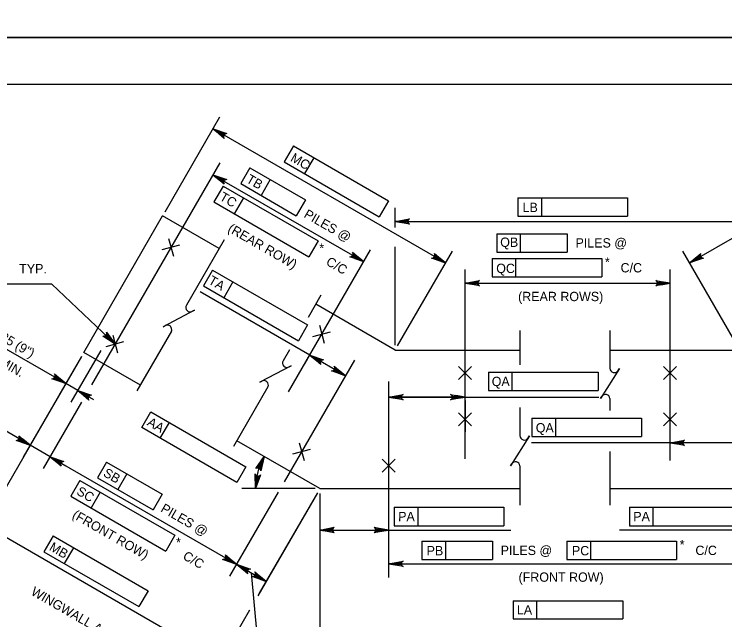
# Model space of a CAD drawing. Extents: x 638340 to 640241, y 295465 to 298435.
# Drawn here: x 639424.7 to 639653.4, y 296465.9 to 296661 of the extents above; entities that cross this region are included whole.
import ezdxf

# ---------------------------------------------------------------- set-up
doc = ezdxf.new("R2010")
doc.units = 0
for name, color, linetype in [('2', 7, 'Continuous'), ('3', 7, 'Continuous'), ('4', 7, 'Continuous'), ('PLT-BNDY', 7, 'Continuous')]:
    doc.layers.add(name, color=color, linetype=linetype)

# ---------------------------------------------------------------- blocks, each defined once
blk = doc.blocks.new('PILE')
at = {"layer": '2'}
for p, q in [((-2.651625, -2.651625), (2.651625, 2.651625)), ((-2.651625, 2.651625), (2.651625, -2.651625))]:
    blk.add_line(p, q, dxfattribs=at)

msp = doc.modelspace()

# ---------------------------------------------------------------- linework, layer by layer
at = {"layer": '2'}
for p, q in [((639316.46, 296638.46), (640102.69, 296638.46)), ((639473.25, 296597.31), (639490.91, 296627.89)), ((639563.54, 296580.84), (639488.7, 296624.05)), ((639642.12, 296580.84), (639716.97, 296624.05)), ((639514.6, 296618.51), (639511.65, 296613.39)), ((639514.6, 296618.51), (639545.17, 296600.85)), ((639490.89, 296613.09), (639449.6, 296541.57)), ((639511.65, 296613.39), (639542.22, 296595.74)), ((639521.15, 296614.72), (639518.2, 296609.61)), ((639500.56, 296611.49), (639497.61, 296606.38)), ((639500.56, 296611.49), (639518.44, 296601.17)), ((639488.68, 296609.26), (639537.18, 296581.25)), ((639497.61, 296606.38), (639515.49, 296596.06)), ((639507.11, 296607.71), (639504.16, 296602.6)), ((639491.96, 296605.59), (639489, 296600.48)), ((639491.96, 296605.59), (639522.52, 296587.93)), ((639498.5, 296601.81), (639495.55, 296596.7)), ((639518.44, 296601.17), (639515.49, 296596.06)), ((639586.82, 296601.76), (639622.12, 296601.76)), ((639586.82, 296601.76), (639586.82, 296595.85)), ((639594.38, 296601.76), (639594.38, 296595.85)), ((639622.12, 296601.76), (639622.12, 296595.85)), ((639489, 296600.48), (639519.57, 296582.81)), ((639545.17, 296600.85), (639542.22, 296595.74)), ((639547.33, 296592.21), (639547.33, 296598.59)), ((639586.82, 296595.85), (639622.12, 296595.85)), ((639547.33, 296594.16), (639658.34, 296594.16)), ((639580.02, 296590.26), (639580.02, 296584.36)), ((639580.02, 296590.26), (639602.72, 296590.26)), ((639587.58, 296590.26), (639587.58, 296584.36)), ((639602.72, 296590.26), (639602.72, 296584.36)), ((639522.52, 296587.93), (639519.57, 296582.81)), ((639547.33, 296554.3), (639547.33, 296586)), ((639513, 296539.37), (639539.4, 296585.09)), ((639548.1, 296554.09), (639565.76, 296584.68)), ((639580.02, 296584.36), (639602.72, 296584.36)), ((639657.57, 296554.09), (639639.91, 296584.68)), ((639578.51, 296582.25), (639613.81, 296582.25)), ((639578.51, 296582.25), (639578.51, 296576.34)), ((639586.07, 296582.25), (639586.07, 296576.34)), ((639613.81, 296582.25), (639613.81, 296576.34)), ((639488.58, 296578.53), (639485.62, 296573.42)), ((639488.58, 296578.53), (639519.14, 296560.86)), ((639569.83, 296517.7), (639569.83, 296578.72)), ((639635.84, 296517.22), (639635.84, 296578.72)), ((639578.51, 296576.34), (639613.81, 296576.34)), ((639495.13, 296574.75), (639492.17, 296569.63)), ((639569.83, 296574.29), (639635.84, 296574.29)), ((639519.82, 296551.18), (639484.54, 296571.54)), ((639485.62, 296573.42), (639516.19, 296555.75)), ((639519.14, 296560.86), (639516.19, 296555.75)), ((639441.31, 296541.99), (639415.68, 296556.79)), ((639518.32, 296548.58), (639522.03, 296555.01)), ((639452.57, 296552.63), (639442.94, 296535.94)), ((639531.34, 296544.52), (639519.82, 296551.18)), ((639446.34, 296550.69), (639412.82, 296492.63)), ((639446.34, 296550.69), (639427.63, 296518.28)), ((639446.34, 296550.69), (639439.1, 296538.15)), ((639534.22, 296549.5), (639511.6, 296510.33)), ((639577.35, 296545.62), (639612.65, 296545.62)), ((639577.35, 296545.62), (639577.35, 296539.71)), ((639584.91, 296545.62), (639584.91, 296539.71)), ((639612.65, 296545.62), (639612.65, 296539.71)), ((639445.15, 296539.77), (639441.32, 296541.99)), ((639545.22, 296542.69), (639545.22, 296479.48)), ((639429.84, 296522.12), (639396.39, 296541.43)), ((639445.15, 296539.77), (639450.27, 296536.82)), ((639577.35, 296539.71), (639612.65, 296539.71)), ((639545.22, 296537.62), (639612.84, 296537.62)), ((639566.88, 296537.62), (639548.18, 296537.62)), ((639446.36, 296535.96), (639434.02, 296514.59)), ((639545.22, 296536.55), (639545.22, 296526.47)), ((639569.83, 296536.55), (639569.83, 296526.47)), ((639465.78, 296527.78), (639468.74, 296532.89)), ((639468.74, 296532.89), (639499.29, 296515.21)), ((639591.33, 296530.89), (639626.63, 296530.89)), ((639591.33, 296530.89), (639591.33, 296524.98)), ((639598.89, 296530.89), (639598.89, 296524.98)), ((639626.63, 296530.89), (639626.63, 296524.98)), ((639471.71, 296524.35), (639474.66, 296529.47)), ((639496.34, 296510.1), (639465.78, 296527.78)), ((639591.33, 296524.98), (639626.63, 296524.98)), ((639436.24, 296518.42), (639429.84, 296522.11)), ((639635.84, 296522.88), (639591.2, 296522.88)), ((639660.44, 296522.88), (639635.84, 296522.88)), ((639436.24, 296518.42), (639496.27, 296483.76)), ((639438.79, 296516.95), (639441.35, 296515.47)), ((639454.47, 296516.7), (639451.51, 296511.59)), ((639454.47, 296516.7), (639472.35, 296506.38)), ((639499.29, 296515.21), (639496.34, 296510.1)), ((639461.01, 296512.93), (639458.06, 296507.81)), ((639445.86, 296510.8), (639442.91, 296505.69)), ((639445.86, 296510.8), (639476.43, 296493.14)), ((639451.51, 296511.59), (639469.39, 296501.27)), ((639521.54, 296508.16), (639497.97, 296508.16)), ((639442.91, 296505.69), (639473.47, 296488.02)), ((639452.41, 296507.02), (639449.46, 296501.91)), ((639472.35, 296506.38), (639469.39, 296501.27)), ((639509.68, 296507), (639494.05, 296479.93)), ((639522.31, 296506.83), (639503.12, 296473.6)), ((639522.31, 296506.83), (639503.59, 296474.42)), ((639523.08, 296506.62), (639523.08, 296460.33)), ((639547.03, 296502.12), (639582.34, 296502.12)), ((639547.03, 296502.12), (639547.03, 296496.21)), ((639554.6, 296502.12), (639554.6, 296496.21)), ((639582.34, 296502.12), (639582.34, 296496.21)), ((639622.71, 296502.12), (639658.01, 296502.12)), ((639622.71, 296502.12), (639622.71, 296496.21)), ((639630.27, 296502.12), (639630.27, 296496.21)), ((639491, 296452.61), (639415.03, 296496.47)), ((639523.08, 296497.73), (639523.08, 296486.65)), ((639547.03, 296496.21), (639582.34, 296496.21)), ((639622.71, 296496.21), (639658.01, 296496.21)), ((639523.08, 296494.81), (639584.61, 296494.81)), ((639682.78, 296494.81), (639619.52, 296494.81)), ((639437.23, 296492.91), (639434.28, 296487.79)), ((639437.23, 296492.91), (639467.81, 296475.25)), ((639476.43, 296493.14), (639473.47, 296488.02)), ((639443.78, 296489.12), (639440.83, 296484.01)), ((639555.94, 296491.22), (639555.94, 296485.31)), ((639555.94, 296491.22), (639578.64, 296491.22)), ((639563.5, 296491.22), (639563.5, 296485.31)), ((639578.64, 296491.22), (639578.64, 296485.31)), ((639602.6, 296491.22), (639637.9, 296491.22)), ((639602.6, 296491.22), (639602.6, 296485.31)), ((639610.16, 296491.22), (639610.16, 296485.31)), ((639637.9, 296491.22), (639637.9, 296485.31)), ((639434.28, 296487.79), (639464.85, 296470.14)), ((639555.94, 296485.31), (639578.64, 296485.31)), ((639602.6, 296485.31), (639637.9, 296485.31)), ((639496.27, 296483.76), (639505.81, 296478.25)), ((639545.22, 296483.91), (639660.44, 296483.91)), ((639500.99, 296481.03), (639502.81, 296461.18)), ((639467.81, 296475.25), (639464.85, 296470.14)), ((639585.28, 296472.05), (639620.58, 296472.05)), ((639585.28, 296472.05), (639585.28, 296466.15)), ((639592.84, 296472.05), (639592.84, 296466.15)), ((639620.58, 296472.05), (639620.58, 296466.15)), ((639500.46, 296468.98), (639488.79, 296448.77)), ((639585.28, 296466.15), (639620.58, 296466.15))]:
    msp.add_line(p, q, dxfattribs=at)
for points in [[(639491.5, 296623), (639491.01, 296622.15), (639488.7, 296624.05)], [(639491.48, 296608.2), (639490.99, 296607.35), (639488.68, 296609.26)], [(639550.28, 296594.65), (639550.28, 296593.67), (639547.33, 296594.16)], [(639534.87, 296583.16), (639534.38, 296582.3), (639537.18, 296581.25)], [(639561.23, 296582.74), (639560.74, 296581.89), (639563.54, 296580.84)], [(639644.43, 296582.74), (639644.93, 296581.89), (639642.12, 296580.84)], [(639572.78, 296574.79), (639572.78, 296573.8), (639569.83, 296574.29)], [(639632.88, 296574.79), (639632.88, 296573.8), (639635.84, 296574.29)], [(639457.19, 296554.72), (639455.22, 296556.93), (639454.88, 296556.58)], [(639522.62, 296550.13), (639522.13, 296549.27), (639519.82, 296551.18)], [(639529.03, 296546.42), (639528.54, 296545.57), (639531.35, 296544.52)], [(639439, 296543.89), (639438.51, 296543.04), (639441.32, 296541.99)], [(639447.95, 296538.72), (639447.46, 296537.87), (639445.15, 296539.77)], [(639548.18, 296538.11), (639548.18, 296537.12), (639545.22, 296537.62)], [(639566.88, 296538.11), (639566.88, 296537.12), (639569.83, 296537.62)], [(639427.53, 296524.02), (639427.04, 296523.16), (639429.84, 296522.11)], [(639638.79, 296523.38), (639638.79, 296522.39), (639635.84, 296522.88)], [(639439.04, 296517.37), (639438.55, 296516.52), (639436.24, 296518.42)], [(639439.04, 296517.37), (639438.55, 296516.52), (639436.24, 296518.42)], [(639526.03, 296495.3), (639526.03, 296494.32), (639523.08, 296494.81)], [(639542.27, 296495.3), (639542.27, 296494.32), (639545.22, 296494.81)], [(639493.95, 296485.67), (639493.46, 296484.81), (639496.27, 296483.76)], [(639499.07, 296482.71), (639498.58, 296481.86), (639496.27, 296483.76)], [(639548.18, 296484.4), (639548.18, 296483.42), (639545.22, 296483.91)], [(639503.5, 296480.15), (639503.01, 296479.3), (639505.81, 296478.25)]]:
    msp.add_lwpolyline(points, close=True, dxfattribs=at)
for points in [[(639488.7, 296624.05), (639493.17, 296622.48), (639492.73, 296622.44), (639492.42, 296622.27), (639492.22, 296622.02), (639492.1, 296621.72), (639492.11, 296621.36), (639492.3, 296620.97), (639488.7, 296624.05), (639492.11, 296621.36), (639492.1, 296621.72), (639488.7, 296624.05), (639492.22, 296622.02), (639492.42, 296622.27), (639488.7, 296624.05), (639492.73, 296622.44)], [(639488.68, 296609.26), (639493.15, 296607.68), (639492.72, 296607.65), (639492.4, 296607.47), (639492.2, 296607.23), (639492.09, 296606.93), (639492.09, 296606.56), (639492.28, 296606.17), (639488.68, 296609.26), (639492.09, 296606.56), (639492.09, 296606.93), (639488.68, 296609.26), (639492.2, 296607.23), (639492.4, 296607.47), (639488.68, 296609.26), (639492.72, 296607.65)], [(639547.33, 296594.16), (639551.99, 296595.04), (639551.63, 296594.79), (639551.45, 296594.47), (639551.39, 296594.16), (639551.45, 296593.85), (639551.63, 296593.54), (639551.99, 296593.29), (639547.33, 296594.16), (639551.63, 296593.54), (639551.45, 296593.85), (639547.33, 296594.16), (639551.39, 296594.16), (639551.45, 296594.47), (639547.33, 296594.16), (639551.63, 296594.79)], [(639537.18, 296581.25), (639532.71, 296582.82), (639533.14, 296582.86), (639533.46, 296583.04), (639533.66, 296583.28), (639533.77, 296583.58), (639533.77, 296583.94), (639533.58, 296584.34), (639537.18, 296581.25), (639533.77, 296583.94), (639533.77, 296583.58), (639537.18, 296581.25), (639533.66, 296583.28), (639533.46, 296583.04), (639537.18, 296581.25), (639533.14, 296582.86)], [(639563.54, 296580.84), (639559.07, 296582.41), (639559.51, 296582.45), (639559.82, 296582.63), (639560.02, 296582.87), (639560.13, 296583.17), (639560.13, 296583.53), (639559.94, 296583.93), (639563.54, 296580.84), (639560.13, 296583.53), (639560.13, 296583.17), (639563.54, 296580.84), (639560.02, 296582.87), (639559.82, 296582.63), (639563.54, 296580.84), (639559.51, 296582.45)], [(639642.12, 296580.84), (639645.72, 296583.93), (639645.54, 296583.53), (639645.53, 296583.17), (639645.64, 296582.87), (639645.84, 296582.63), (639646.16, 296582.45), (639646.6, 296582.41), (639642.12, 296580.84), (639646.16, 296582.45), (639645.84, 296582.63), (639642.12, 296580.84), (639645.64, 296582.87), (639645.53, 296583.17), (639642.12, 296580.84), (639645.54, 296583.53)], [(639457.19, 296554.72), (639436.85, 296574.04), (639370.27, 296574.04)], [(639569.83, 296574.29), (639574.49, 296575.17), (639574.13, 296574.92), (639573.95, 296574.61), (639573.89, 296574.29), (639573.95, 296573.98), (639574.13, 296573.67), (639574.49, 296573.42), (639569.83, 296574.29), (639574.13, 296573.67), (639573.95, 296573.98), (639569.83, 296574.29), (639573.89, 296574.29), (639573.95, 296574.61), (639569.83, 296574.29), (639574.13, 296574.92)], [(639635.84, 296574.29), (639631.18, 296573.42), (639631.53, 296573.67), (639631.72, 296573.98), (639631.77, 296574.29), (639631.72, 296574.61), (639631.53, 296574.92), (639631.18, 296575.17), (639635.84, 296574.29), (639631.53, 296574.92), (639631.72, 296574.61), (639635.84, 296574.29), (639631.77, 296574.29), (639631.72, 296573.98), (639635.84, 296574.29), (639631.53, 296573.67)], [(639457.19, 296554.72), (639453.21, 296557.3), (639453.64, 296557.23), (639453.99, 296557.33), (639454.25, 296557.52), (639454.42, 296557.78), (639454.5, 296558.14), (639454.42, 296558.57), (639457.19, 296554.72), (639454.5, 296558.14), (639454.42, 296557.78), (639457.19, 296554.72), (639454.25, 296557.52), (639453.99, 296557.33), (639457.19, 296554.72), (639453.64, 296557.23)], [(639519.82, 296551.18), (639524.29, 296549.6), (639523.85, 296549.57), (639523.54, 296549.39), (639523.34, 296549.15), (639523.22, 296548.85), (639523.23, 296548.49), (639523.41, 296548.09), (639519.82, 296551.18), (639523.23, 296548.49), (639523.22, 296548.85), (639519.82, 296551.18), (639523.34, 296549.15), (639523.54, 296549.39), (639519.82, 296551.18), (639523.85, 296549.57)], [(639531.34, 296544.52), (639526.87, 296546.09), (639527.31, 296546.13), (639527.62, 296546.31), (639527.82, 296546.55), (639527.94, 296546.85), (639527.93, 296547.21), (639527.75, 296547.61), (639531.34, 296544.52), (639527.93, 296547.21), (639527.94, 296546.85), (639531.34, 296544.52), (639527.82, 296546.55), (639527.62, 296546.31), (639531.34, 296544.52), (639527.31, 296546.13)], [(639441.31, 296541.99), (639436.84, 296543.56), (639437.28, 296543.6), (639437.59, 296543.77), (639437.8, 296544.02), (639437.91, 296544.32), (639437.9, 296544.68), (639437.72, 296545.07), (639441.31, 296541.99), (639437.9, 296544.68), (639437.91, 296544.32), (639441.31, 296541.99), (639437.8, 296544.02), (639437.59, 296543.77), (639441.31, 296541.99), (639437.28, 296543.6)], [(639445.15, 296539.77), (639449.63, 296538.2), (639449.19, 296538.16), (639448.87, 296537.98), (639448.67, 296537.74), (639448.56, 296537.44), (639448.57, 296537.08), (639448.75, 296536.68), (639445.15, 296539.77), (639448.57, 296537.08), (639448.56, 296537.44), (639445.15, 296539.77), (639448.67, 296537.74), (639448.87, 296537.98), (639445.15, 296539.77), (639449.19, 296538.16)], [(639545.22, 296537.62), (639549.88, 296538.49), (639549.53, 296538.24), (639549.34, 296537.93), (639549.29, 296537.62), (639549.34, 296537.3), (639549.53, 296536.99), (639549.88, 296536.74), (639545.22, 296537.62), (639549.53, 296536.99), (639549.34, 296537.3), (639545.22, 296537.62), (639549.29, 296537.62), (639549.34, 296537.93), (639545.22, 296537.62), (639549.53, 296538.24)], [(639569.83, 296537.62), (639565.17, 296536.74), (639565.53, 296536.99), (639565.71, 296537.3), (639565.77, 296537.62), (639565.71, 296537.93), (639565.53, 296538.24), (639565.17, 296538.49), (639569.83, 296537.62), (639565.53, 296538.24), (639565.71, 296537.93), (639569.83, 296537.62), (639565.77, 296537.62), (639565.71, 296537.3), (639569.83, 296537.62), (639565.53, 296536.99)], [(639429.84, 296522.12), (639425.37, 296523.69), (639425.8, 296523.72), (639426.12, 296523.9), (639426.32, 296524.15), (639426.43, 296524.44), (639426.43, 296524.81), (639426.24, 296525.2), (639429.84, 296522.12), (639426.43, 296524.81), (639426.43, 296524.44), (639429.84, 296522.12), (639426.32, 296524.15), (639426.12, 296523.9), (639429.84, 296522.12), (639425.8, 296523.72)], [(639635.84, 296522.88), (639640.5, 296523.76), (639640.14, 296523.51), (639639.95, 296523.2), (639639.9, 296522.88), (639639.95, 296522.57), (639640.14, 296522.26), (639640.5, 296522.01), (639635.84, 296522.88), (639640.14, 296522.26), (639639.95, 296522.57), (639635.84, 296522.88), (639639.9, 296522.88), (639639.95, 296523.2), (639635.84, 296522.88), (639640.14, 296523.51)], [(639635.84, 296522.88), (639640.5, 296523.76), (639640.14, 296523.51), (639639.95, 296523.2), (639639.9, 296522.88), (639639.95, 296522.57), (639640.14, 296522.26), (639640.5, 296522.01), (639635.84, 296522.88), (639640.14, 296522.26), (639639.95, 296522.57), (639635.84, 296522.88), (639639.9, 296522.88), (639639.95, 296523.2), (639635.84, 296522.88), (639640.14, 296523.51)], [(639436.24, 296518.42), (639440.71, 296516.85), (639440.27, 296516.81), (639439.96, 296516.63), (639439.75, 296516.39), (639439.64, 296516.09), (639439.65, 296515.73), (639439.84, 296515.33), (639436.24, 296518.42), (639439.65, 296515.73), (639439.64, 296516.09), (639436.24, 296518.42), (639439.75, 296516.39), (639439.96, 296516.63), (639436.24, 296518.42), (639440.27, 296516.81)], [(639505.17, 296518.5), (639504.09, 296513.89), (639504.01, 296514.31), (639503.8, 296514.61), (639503.53, 296514.78), (639503.22, 296514.86), (639502.86, 296514.82), (639502.49, 296514.59), (639505.17, 296518.5), (639502.86, 296514.82), (639503.22, 296514.86), (639505.17, 296518.5), (639503.53, 296514.78), (639503.8, 296514.61), (639505.17, 296518.5), (639504.01, 296514.31)], [(639502.38, 296508.16), (639502.25, 296512.9), (639502.44, 296512.51), (639502.72, 296512.28), (639503.02, 296512.17), (639503.34, 296512.18), (639503.68, 296512.31), (639503.98, 296512.63), (639502.38, 296508.16), (639503.68, 296512.31), (639503.34, 296512.18), (639502.38, 296508.16), (639503.02, 296512.17), (639502.72, 296512.28), (639502.38, 296508.16), (639502.44, 296512.51)], [(639523.08, 296494.81), (639527.74, 296495.68), (639527.38, 296495.44), (639527.19, 296495.12), (639527.14, 296494.81), (639527.19, 296494.5), (639527.38, 296494.19), (639527.74, 296493.94), (639523.08, 296494.81), (639527.38, 296494.19), (639527.19, 296494.5), (639523.08, 296494.81), (639527.14, 296494.81), (639527.19, 296495.12), (639523.08, 296494.81), (639527.38, 296495.44)], [(639545.22, 296494.81), (639540.56, 296493.94), (639540.92, 296494.19), (639541.11, 296494.5), (639541.16, 296494.81), (639541.11, 296495.12), (639540.92, 296495.44), (639540.56, 296495.68), (639545.22, 296494.81), (639540.92, 296495.44), (639541.11, 296495.12), (639545.22, 296494.81), (639541.16, 296494.81), (639541.11, 296494.5), (639545.22, 296494.81), (639540.92, 296494.19)], [(639496.27, 296483.76), (639491.79, 296485.34), (639492.23, 296485.37), (639492.55, 296485.55), (639492.75, 296485.79), (639492.86, 296486.09), (639492.85, 296486.46), (639492.67, 296486.85), (639496.27, 296483.76), (639492.85, 296486.46), (639492.86, 296486.09), (639496.27, 296483.76), (639492.75, 296485.79), (639492.55, 296485.55), (639496.27, 296483.76), (639492.23, 296485.37)], [(639545.22, 296483.91), (639549.88, 296484.78), (639549.53, 296484.54), (639549.34, 296484.22), (639549.29, 296483.91), (639549.34, 296483.6), (639549.53, 296483.29), (639549.88, 296483.04), (639545.22, 296483.91), (639549.53, 296483.29), (639549.34, 296483.6), (639545.22, 296483.91), (639549.29, 296483.91), (639549.34, 296484.22), (639545.22, 296483.91), (639549.53, 296484.54)], [(639496.27, 296483.76), (639500.74, 296482.19), (639500.3, 296482.15), (639499.99, 296481.98), (639499.79, 296481.73), (639499.68, 296481.43), (639499.68, 296481.07), (639499.87, 296480.68), (639496.27, 296483.76), (639499.68, 296481.07), (639499.68, 296481.43), (639496.27, 296483.76), (639499.79, 296481.73), (639499.99, 296481.98), (639496.27, 296483.76), (639500.3, 296482.15)], [(639505.81, 296478.25), (639501.34, 296479.83), (639501.77, 296479.86), (639502.09, 296480.04), (639502.29, 296480.28), (639502.4, 296480.58), (639502.4, 296480.94), (639502.21, 296481.34), (639505.81, 296478.25), (639502.4, 296480.94), (639502.4, 296480.58), (639505.81, 296478.25), (639502.29, 296480.28), (639502.09, 296480.04), (639505.81, 296478.25), (639501.77, 296479.86)]]:
    msp.add_lwpolyline(points, dxfattribs=at)
msp.add_arc((639523.08, 296508.16), 20.68, 149.9993, 179.9986, dxfattribs=at)
at = {"layer": '3'}
for p, q in [((639447.11, 296552.02), (639472.48, 296595.97)), ((639490.68, 296585.47), (639472.48, 296595.97)), ((639547.33, 296552.76), (639521.76, 296567.53)), ((639465.31, 296541.51), (639447.11, 296552.02)), ((639547.33, 296552.76), (639587.5, 296552.76)), ((639616.47, 296552.76), (639658.34, 296552.76)), ((639523.08, 296508.16), (639496.38, 296523.57)), ((639523.08, 296508.16), (639587.5, 296508.16)), ((639616.47, 296508.16), (639682.59, 296508.16))]:
    msp.add_line(p, q, dxfattribs=at)
at = {"layer": '4'}
for p, q in [((639492.33, 296588.33), (639480.15, 296567.22)), ((639523.44, 296570.43), (639519.32, 296563.3)), ((639475.29, 296558.81), (639464.23, 296539.66)), ((639587.5, 296559.03), (639587.5, 296547.98)), ((639616.47, 296559.03), (639616.47, 296546.91)), ((639513.31, 296552.89), (639511.25, 296549.32)), ((639506.39, 296540.91), (639495.34, 296521.76)), ((639616.47, 296537.2), (639616.47, 296533.26)), ((639587.5, 296534.26), (639587.5, 296525.22)), ((639616.47, 296520.05), (639616.47, 296502.82)), ((639587.5, 296515.5), (639587.5, 296502.82))]:
    msp.add_line(p, q, dxfattribs=at)
for points in [[(639482.09, 296565.28), (639482.71, 296565.61), (639472.66, 296560.3), (639473.33, 296560.66)], [(639513.19, 296547.38), (639513.82, 296547.72), (639503.77, 296542.41), (639504.44, 296542.76)], [(639619.13, 296546.2), (639619.5, 296546.8), (639613.45, 296537.18), (639613.86, 296537.82)], [(639590.15, 296524.5), (639590.53, 296525.1), (639584.48, 296515.48), (639584.88, 296516.13)]]:
    msp.add_lwpolyline(points, dxfattribs=at)
for centre, start, end in [((639481.38, 296566.51), 150, 300), ((639474, 296559.4), 335.3286, 117.8672), ((639512.48, 296548.61), 150, 300), ((639617.9, 296546.91), 180, 330), ((639505.1, 296541.51), 335.3286, 117.8672), ((639615.06, 296537.07), 5.3286, 147.8672), ((639588.92, 296525.22), 180, 330), ((639586.09, 296515.37), 5.3286, 147.8672)]:
    msp.add_arc(centre, 1.42, start, end, dxfattribs=at)
at = {"layer": 'PLT-BNDY'}
for points in [[(639276.46, 297247.46), (640117.46, 297247.46), (640117.46, 296653.46), (639276.46, 296653.46)], [(639276.46, 296653.46), (640117.46, 296653.46), (640117.46, 296059.46), (639276.46, 296059.46)]]:
    msp.add_lwpolyline(points, close=True, dxfattribs=at)

# ---------------------------------------------------------------- block references
at = {"layer": '2', "xscale": 0.7874360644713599, "yscale": 0.78743606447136, "rotation": -30.00000000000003}
for p in [(639475.19, 296585.89), (639523.69, 296557.89), (639457.19, 296554.72), (639517.23, 296520.06)]:
    msp.add_blockref('PILE', p, dxfattribs=at)
at = {"layer": '2', "xscale": 0.78743606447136, "yscale": 0.78743606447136}
for p in [(639569.83, 296545.38), (639635.84, 296545.38), (639569.83, 296530.46), (639635.84, 296530.46), (639545.23, 296515.54)]:
    msp.add_blockref('PILE', p, dxfattribs=at)

# ---------------------------------------------------------------- texts
at = {"layer": '2'}
for s, height, rotation, p in [('MC', 3, 329.9382, (639513.38, 296613.82)), ('TB', 3, 329.9382, (639499.15, 296606.97)), ('TC', 3, 329.9382, (639490.54, 296601.27)), ('LB', 3, 359.9382, (639588.35, 296597.24)), ('PILES @', 3, 330, (639517.71, 296595.7)), ('(REAR ROW)', 3, 330, (639493.21, 296591.12)), ('QB', 3, 359.9382, (639581.14, 296586.01)), ('PILES @', 3, 359.9382, (639605.38, 296585.81)), ('*', 3, 359.9382, (639522.91, 296584.1)), ('C/C', 3, 329.9382, (639524.81, 296580.42)), ('QC', 3, 359.9382, (639579.86, 296577.59)), ('*', 3, 359.9382, (639614.84, 296579.65)), ('C/C', 3, 359.9382, (639619.89, 296577.79)), ('TA', 3, 329.9382, (639486.94, 296574.34)), ('225 (9")', 3, 330, (639417.96, 296557.23)), ('MIN.', 3, 330, (639419.52, 296548.16)), ('QA', 3, 359.9382, (639578.41, 296541.17)), ('AA', 3, 329.9509, (639467.25, 296528.71)), ('QA', 3, 359.9382, (639592.59, 296526.24)), ('SB', 3, 329.9382, (639453.12, 296512.35)), ('SC', 3, 329.9382, (639444.51, 296506.44)), ('PILES @', 3, 330, (639471.61, 296500.92)), ('(FRONT ROW)', 3.0001, 330, (639443.13, 296498.89)), ('PA', 3, 359.9382, (639548.29, 296497.66)), ('PA', 3, 359.9382, (639623.97, 296497.66)), ('*', 3, 359.9382, (639476.81, 296489.31)), ('*', 3, 359.9382, (639638.92, 296488.62)), ('MB', 3, 329.9382, (639435.75, 296488.48)), ('PB', 3, 359.9382, (639557.46, 296486.66)), ('PILES @', 3, 359.9382, (639581.29, 296486.76)), ('PC', 3, 359.9382, (639604.22, 296486.66)), ('C/C', 3, 359.9382, (639643.97, 296486.76)), ('C/C', 3, 329.9382, (639478.72, 296485.63)), ('WINGWALL A', 3, 330, (639429.85, 296474.11)), ('LA', 3, 359.9382, (639586.5, 296467.6))]:
    msp.add_text(s, height=height, rotation=rotation, dxfattribs=at).set_placement(p)
for s, height, p in [('TYP.', 3, (639426.31, 296577.49)), ('(REAR ROWS)', 3.0001, (639586.9, 296568.53)), ('(FRONT ROW)', 3.0001, (639587.04, 296478.14))]:
    msp.add_text(s, height=height, dxfattribs=at).set_placement(p)

doc.saveas('drawing.dxf')
